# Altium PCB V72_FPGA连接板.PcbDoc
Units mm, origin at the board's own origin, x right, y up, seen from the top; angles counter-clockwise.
Board outline 27.69 x 52.7 mm, 2 copper layers (Top Layer, Bottom Layer); 0 components, 31 nets, 94 pads, 2 vias.
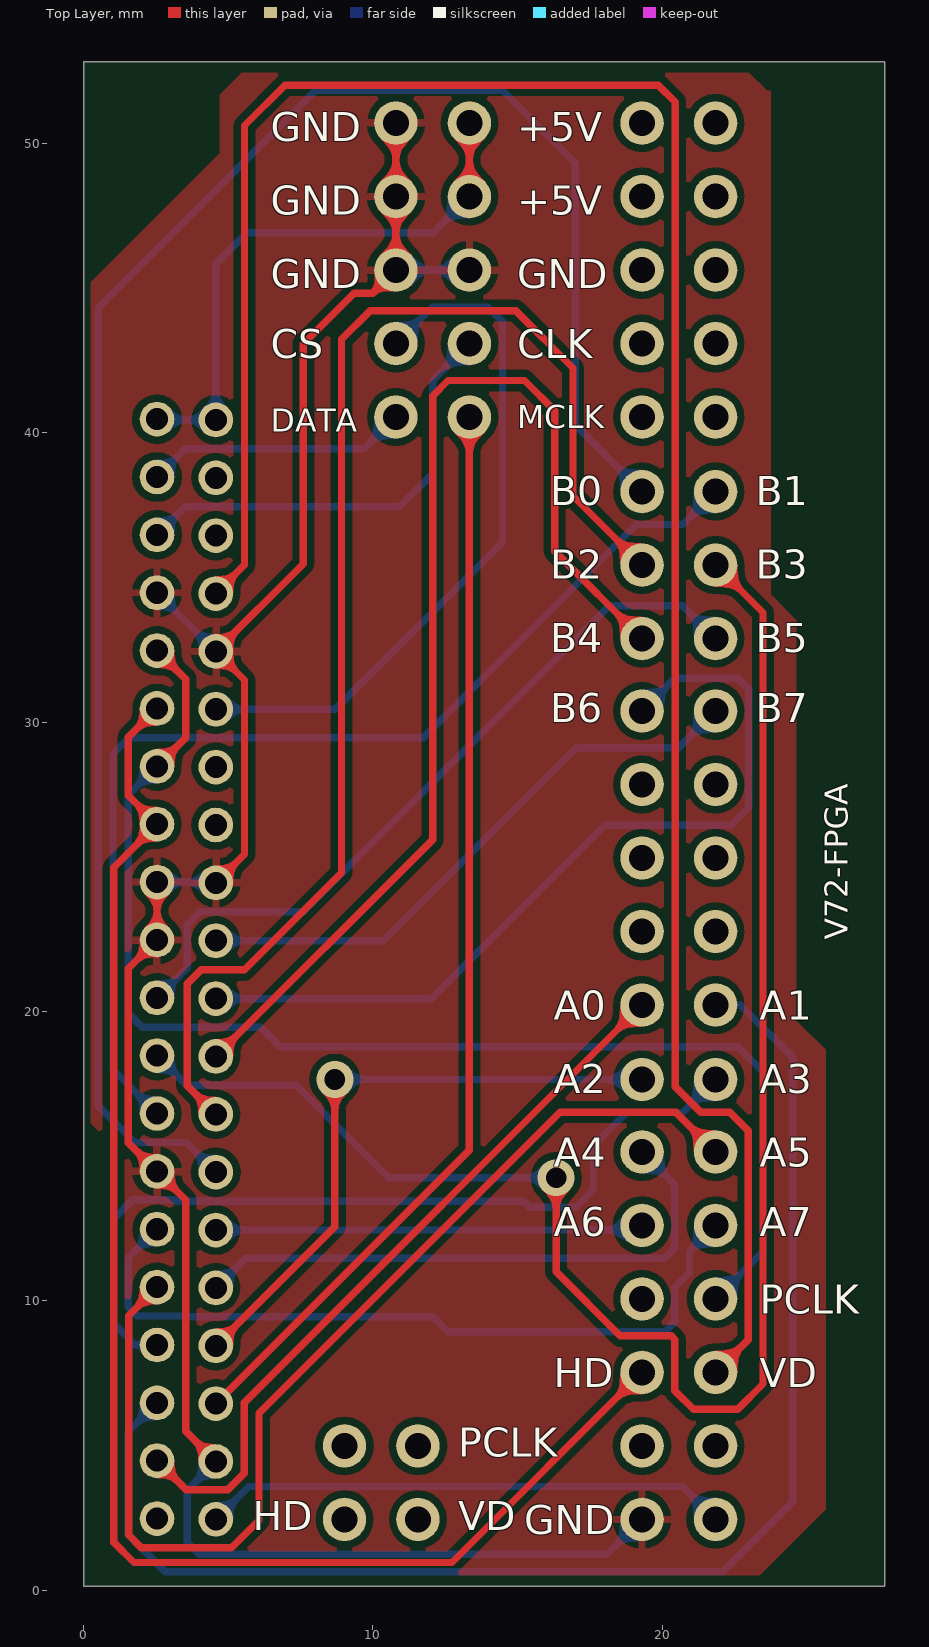
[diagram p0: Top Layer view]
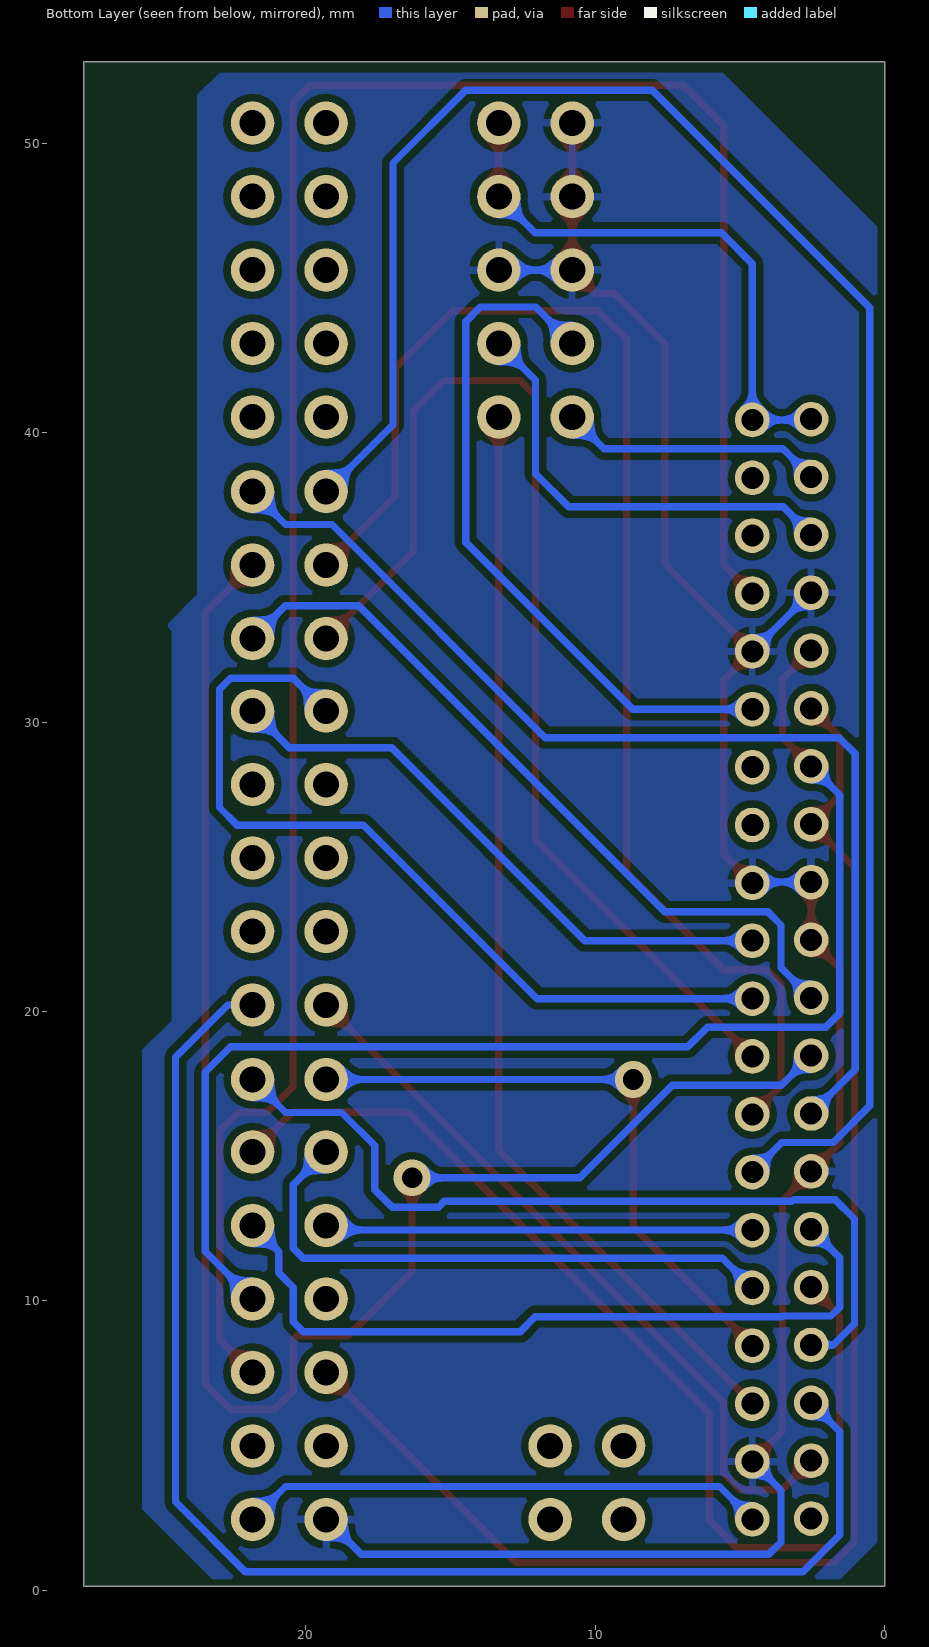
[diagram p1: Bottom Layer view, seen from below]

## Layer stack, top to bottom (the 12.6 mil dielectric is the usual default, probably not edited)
Top Solder: solder mask 0.0102, Solder Resist, Dk 3.5
Top Layer: signal copper 0.0356
Dielectric 1: dielectric 0.32, FR-4, Dk 4.8
Bottom Layer: signal copper 0.0356
Bottom Solder: solder mask 0.0102, Solder Resist, Dk 3.5

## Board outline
0,0.127 0,52.832 27.686,52.832 27.686,0.127

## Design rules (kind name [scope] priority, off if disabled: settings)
Clearance [All] p1: gap=0.254 ignorepadtopadclearanceinfootprint=FALSE except(0: Arc-Hole Track-Hole SMDPad-Hole THPad-Hole Via-Hole Fill-Hole Poly-Hole Region-Hole Text-Hole)
PolygonConnect [All] p1: connectstyle=Relief reliefconductorwidth=0.254 reliefentries=4 polygonreliefangle="90 Angle" airgapwidth=0.254
RoutingVias [All] p1: holewidth=0.711 width=1.27 viastyle="Through Hole" minholewidth=0.711 minwidth=1.27 maxholewidth=0.711 maxwidth=1.27
SolderMaskExpansion [All] p1: expansion=0.102
Width [All] p1: maxlimit=0.254 minlimit=0.254 preferedwidth=0.254
30 further rules are at their usual default settings.

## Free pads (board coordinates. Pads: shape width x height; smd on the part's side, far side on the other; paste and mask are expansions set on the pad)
  round 1.2 hole 0.762: 1(2.539,40.473) 2(4.572,40.445) 3(2.539,38.473) 4(4.572,38.445) 5(2.539,36.473) 6(4.572,36.445) 7(2.539,34.473) 8(4.572,34.445) 9(2.539,32.473) 10(4.572,32.445) 11(2.539,30.473) 12(4.572,30.445) 13(2.539,28.473) 14(4.572,28.445) 15(2.539,26.473) 16(4.572,26.445) 17(2.539,24.473) 18(4.572,24.445) 19(2.539,22.473) 20(4.572,22.445) 21(2.539,20.473) 22(4.572,20.445) 23(2.539,18.473) 24(4.572,18.445) 25(2.539,16.473) 26(4.572,16.445) 27(2.539,14.473) 28(4.572,14.445) 29(2.539,12.473) 30(4.572,12.445) 31(2.539,10.473) 32(4.572,10.445) 33(2.539,8.473) 34(4.572,8.445) 35(2.539,6.473) 36(4.572,6.445) 37(2.539,4.473) 38(4.572,4.445) 39(2.539,2.473) 40(4.572,2.445)
  round 1.5 hole 0.9: 1(21.844,2.445) 2(19.304,2.445) 3(21.844,4.985) 4(19.304,4.985) 5(11.557,2.445) 5(21.844,7.525) 6(9.017,2.445) 6(19.304,7.525) 7(11.557,4.985) 7(21.844,10.065) 8(9.017,4.985) 8(19.304,10.065) 9(21.844,12.605) 10(19.304,12.605) 11(21.844,15.145) 12(19.304,15.145) 13(21.844,17.649) 14(19.304,17.649) 15(21.844,20.225) 16(19.304,20.225) 17(21.844,22.765) 18(19.304,22.765) 19(21.844,25.305) 20(19.304,25.305) 21(21.844,27.845) 22(19.304,27.845) 23(21.844,30.385) 24(19.304,30.385) 25(21.844,32.889) 26(19.304,32.889) 27(21.844,35.429) 28(19.304,35.429) 29(21.844,37.969) 30(19.304,37.969) 31(13.335,40.545) 31(21.844,40.545) 32(10.795,40.545) 32(19.304,40.545) 33(13.335,43.085) 33(21.844,43.085) 34(10.795,43.085) 34(19.304,43.085) 35(13.335,45.625) 35(21.844,45.625) 36(10.795,45.625) 36(19.304,45.625) 37(13.335,48.165) 37(21.844,48.165) 38(10.795,48.165) 38(19.304,48.165) 39(13.335,50.705) 39(21.844,50.705) 40(10.795,50.705) 40(19.304,50.705)

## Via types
v1: diameter 1.27, hole 0.711, Top Layer to Bottom Layer, 2 vias

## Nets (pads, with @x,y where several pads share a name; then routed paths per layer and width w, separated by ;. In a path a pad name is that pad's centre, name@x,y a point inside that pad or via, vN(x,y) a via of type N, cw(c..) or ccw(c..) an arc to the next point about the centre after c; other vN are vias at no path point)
+5V: pad.1@2.539,40.473 pad.2@4.572,40.445 pad.37@13.335,48.165 pad.39@13.335,50.705 | length 19.7
  Top Layer w0.254: pad.37@13.335,48.165 pad.39@13.335,50.705
  Bottom Layer w0.254: pad.1@2.539,40.473 2.539,40.445 4.572,40.445 4.572,45.847 5.639,46.914 12.084,46.914 pad.37@13.335,48.165
A0: pad.16@19.304,20.225 pad.37@2.539,4.473 | length 25.6
  Top Layer w0.254: pad.37@2.539,4.473 3.548,3.464 4.978,3.464 5.553,4.039 5.553,6.474 pad.16@19.304,20.225
A1: pad.15@21.844,20.225 pad.35@2.539,6.473 | length 48.2
  Bottom Layer w0.254: pad.35@2.539,6.473 1.549,5.483 1.549,1.905 2.819,0.635 22.098,0.635 24.511,3.048 24.511,18.415 22.701,20.225 pad.15@21.844,20.225
A2: pad.14@19.304,17.649 pad.34@4.572,8.445 | length 21.5
  Top Layer w0.254: pad.34@4.572,8.445 8.687,12.56 v1(8.687,17.649)
  Bottom Layer w0.254: v1(8.687,17.649) pad.14@19.304,17.649
A3: pad.13@21.844,17.649 pad.33@2.539,8.473 | length 29.3
  Bottom Layer w0.254: pad.33@2.539,8.473 1.778,8.473 1.041,9.21 1.041,12.827 1.702,13.487 3.15,13.487 3.2,13.437 15.215,13.437 15.418,13.233 17.018,13.233 17.628,13.843 17.628,15.367 18.771,16.51 20.705,16.51 pad.13@21.844,17.649
A4: pad.12@19.304,15.145 pad.32@4.572,10.445 | length 20.2
  Bottom Layer w0.254: pad.32@4.572,10.445 5.601,11.474 20.098,11.474 20.435,11.811 20.435,14.014 pad.12@19.304,15.145
A5: pad.11@21.844,15.145 pad.31@2.539,10.473 | length 38.4
  Top Layer w0.254: pad.31@2.539,10.473 1.558,9.492 1.558,1.905 1.999,1.464 5.112,1.464 6.061,2.413 6.061,6.112 16.467,16.518 20.471,16.518 pad.11@21.844,15.145
A6: pad.10@19.304,12.605 pad.30@4.572,12.445 | length 14.8
  Bottom Layer w0.254: pad.30@4.572,12.445 19.144,12.445 pad.10@19.304,12.605
A7: pad.9@21.844,12.605 pad.29@2.539,12.473 | length 26.4
  Bottom Layer w0.254: pad.29@2.539,12.473 1.549,11.483 1.549,9.779 1.854,9.474 3.531,9.474 3.556,9.449 12.084,9.449 12.598,8.934 20.098,8.934 20.435,9.271 20.435,10.458 20.943,10.966 20.943,11.704 pad.9@21.844,12.605
B0: pad.28@4.572,14.445 pad.30@19.304,37.969 | length 65.6
  Bottom Layer w0.254: pad.28@4.572,14.445 3.548,15.469 1.778,15.469 0.508,16.739 0.508,44.323 8.026,51.841 14.478,51.841 16.993,49.327 16.993,40.28 pad.30@19.304,37.969
B1: pad.25@2.539,16.473 pad.29@21.844,37.969 | length 37.6
  Bottom Layer w0.254: pad.25@2.539,16.473 1.016,17.996 1.016,28.905 1.575,29.464 11.735,29.464 19.101,36.83 20.705,36.83 pad.29@21.844,37.969
B2: pad.26@4.572,16.445 pad.28@19.304,35.429 | length 47.3
  Top Layer w0.254: pad.26@4.572,16.445 3.581,17.436 3.581,20.955 4.064,21.438 5.563,21.438 8.915,24.79 8.915,43.231 9.906,44.221 14.935,44.221 16.916,42.24 16.916,37.817 pad.28@19.304,35.429
B3: pad.23@2.539,18.473 pad.27@21.844,35.429 | length 58.3
  Top Layer w0.254: v1(16.332,14.249) 16.332,10.998 18.542,8.788 20.308,8.788 20.435,8.661 20.435,6.895 21.082,6.248 22.606,6.248 23.483,7.125 23.483,33.79 pad.27@21.844,35.429
  Bottom Layer w0.254: pad.23@2.539,18.473 3.562,17.45 7.341,17.45 10.541,14.249 v1(16.332,14.249)
B4: pad.24@4.572,18.445 pad.26@19.304,32.889 | length 39.9
  Top Layer w0.254: pad.24@4.572,18.445 12.065,25.938 12.065,41.275 12.598,41.808 15.24,41.808 16.281,40.767 16.281,35.912 pad.26@19.304,32.889
B5: pad.21@2.539,20.473 pad.25@21.844,32.889 | length 26.2
  Bottom Layer w0.254: pad.21@2.539,20.473 3.581,21.515 3.581,22.987 4.039,23.444 7.595,23.444 18.17,34.02 20.713,34.02 pad.25@21.844,32.889
B6: pad.22@4.572,20.445 pad.24@19.304,30.385 | length 29.5
  Bottom Layer w0.254: pad.22@4.572,20.445 12.012,20.445 18.009,26.441 22.377,26.441 22.987,27.051 22.987,31.135 22.606,31.516 20.435,31.516 pad.24@19.304,30.385
B7: pad.20@4.572,22.445 pad.23@21.844,30.385 | length 20.6
  Bottom Layer w0.254: pad.20@4.572,22.445 10.363,22.445 17.033,29.115 20.574,29.115 pad.23@21.844,30.385
CS_SPI: pad.12@4.572,30.445 pad.34@10.795,43.085 | length 24.3
  Bottom Layer w0.254: pad.12@4.572,30.445 8.703,30.445 14.478,36.22 14.478,43.84 13.97,44.348 12.058,44.348 pad.34@10.795,43.085
FRAME_START: pad.16@4.572,26.445
GND: pad.2@19.304,2.445 pad.7@2.539,34.473 pad.10@4.572,32.445 pad.17@2.539,24.473 pad.18@4.572,24.445 pad.19@2.539,22.473 pad.27@2.539,14.473 pad.35@13.335,45.625 pad.36@10.795,45.625 pad.38@4.572,4.445 pad.38@10.795,48.165 pad.40@10.795,50.705 | length 78.8
  Top Layer w0.254: pad.17@2.539,24.473 2.539,22.473 1.549,21.483 1.549,15.463 2.539,14.473 3.531,13.481 3.531,5.486 pad.38@4.572,4.445 ; pad.18@4.572,24.445 5.563,25.436 5.563,31.454 4.572,32.445 7.595,35.468 7.595,43.071 9.347,44.823 9.993,44.823 10.795,45.625 10.795,48.165 pad.40@10.795,50.705
  Bottom Layer w0.254: pad.17@2.539,24.473 4.572,24.473 pad.18@4.572,24.445 ; pad.7@2.539,34.473 3.535,33.477 3.54,33.477 pad.10@4.572,32.445 ; pad.38@4.572,4.445 3.581,3.454 3.581,1.651 3.998,1.234 18.093,1.234 pad.2@19.304,2.445 ; pad.36@10.795,45.625 pad.35@13.335,45.625
HD: pad.6@19.304,7.525 pad.11@2.539,30.473 pad.15@2.539,26.473 | length 51.5
  Top Layer w0.254: pad.11@2.539,30.473 1.549,29.483 1.549,27.463 2.539,26.473 1.041,24.975 1.041,1.66 1.745,0.956 12.735,0.956 pad.6@19.304,7.525
I2C_CLK(SCL): pad.5@2.539,36.473 pad.33@13.335,43.085 | length 15.4
  Bottom Layer w0.254: pad.5@2.539,36.473 3.506,37.44 10.922,37.44 12.065,38.583 12.065,41.815 pad.33@13.335,43.085
I2C_Data(SDI): pad.3@2.539,38.473 pad.32@10.795,40.545 | length 9.1
  Bottom Layer w0.254: pad.3@2.539,38.473 3.512,39.446 9.696,39.446 pad.32@10.795,40.545
MAIN_RES: pad.6@4.572,36.445
MCLK: pad.31@13.335,40.545 pad.36@4.572,6.445 | length 37.7
  Top Layer w0.254: pad.36@4.572,6.445 13.335,15.208 pad.31@13.335,40.545
MODULE_RST: pad.4@4.572,38.445
PCLK: pad.7@21.844,10.065 pad.9@2.539,32.473 pad.13@2.539,28.473 | length 45.1
  Top Layer w0.254: pad.13@2.539,28.473 3.531,29.465 3.531,31.481 pad.9@2.539,32.473
  Bottom Layer w0.254: pad.13@2.539,28.473 1.549,27.483 1.549,19.939 2.032,19.456 6.121,19.456 6.798,18.78 22.61,18.78 23.483,17.907 23.483,11.704 pad.7@21.844,10.065
ROLLER_OUT: pad.14@4.572,28.445
TP0: pad.39@2.539,2.473
TP1: pad.1@21.844,2.445 pad.40@4.572,2.445 | length 18.2
  Bottom Layer w0.254: pad.40@4.572,2.445 5.708,3.581 20.708,3.581 pad.1@21.844,2.445
VD: pad.5@21.844,7.525 pad.8@4.572,34.445 | length 78.3
  Top Layer w0.254: pad.8@4.572,34.445 5.563,35.436 5.563,50.622 6.96,52.019 19.863,52.019 20.447,51.435 20.447,17.399 21.328,16.518 22.332,16.518 22.975,15.875 22.975,8.656 pad.5@21.844,7.525

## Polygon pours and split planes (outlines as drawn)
GND on Top Layer "Top Layer-GND" (solid, pour order 0): 22.987,52.451 23.622,51.816 23.749,51.816 23.749,34.417 24.638,33.528 24.638,19.685 25.654,18.669 25.654,2.794 23.368,0.508 1.651,0.508 0.635,1.524 0.635,15.748 0.254,16.129 0.254,45.212 4.699,49.657 4.699,51.689 5.461,52.451
GND on Bottom Layer "Top Layer-GND" (solid, pour order 2): 5.588,52.451 22.987,52.451 23.749,51.689 23.749,34.417 24.765,33.401 24.765,33.274 24.638,33.147 24.638,19.685 25.654,18.669 25.654,2.794 23.241,0.381 1.524,0.381 0.254,1.651 0.254,47.117

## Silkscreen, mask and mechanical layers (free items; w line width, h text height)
Top Overlay:
  text "GND" at 6.477,50.07 h1
  text "+5V" at 14.986,50.07 h1
  text "GND" at 6.477,47.53 h1
  text "+5V" at 14.986,47.53 h1
  text "GND" at 6.477,44.99 h1
  text "GND" at 14.986,44.99 h1
  text "CS" at 6.477,42.577 h1
  text "CLK" at 14.986,42.577 h1
  text "MCLK" at 14.986,40.164 h0.8
  text "DATA" at 6.477,40.037 h0.8
  text "B0" at 16.129,37.497 h1
  text "B1" at 23.241,37.497 h1
  text "B2" at 16.129,34.957 h1
  text "B3" at 23.241,34.957 h1
  text "B4" at 16.129,32.417 h1
  text "B5" at 23.241,32.417 h1
  text "B6" at 16.129,30.004 h1
  text "B7" at 23.241,30.004 h1
  text "V72-FPGA" at 26.416,22.479 h0.8 r90
  text "A0" at 16.256,19.717 h1
  text "A1" at 23.368,19.717 h1
  text "A2" at 16.256,17.177 h1
  text "A3" at 23.368,17.177 h1
  text "A4" at 16.256,14.637 h1
  text "A5" at 23.368,14.637 h1
  text "A6" at 16.256,12.224 h1
  text "A7" at 23.368,12.224 h1
  text "PCLK" at 23.368,9.557 h1
  text "HD" at 16.256,7.017 h1
  text "VD" at 23.368,7.017 h1
  text "PCLK" at 12.954,4.604 h1
  text "HD" at 5.842,2.064 h1
  text "VD" at 12.954,2.064 h1
  text "GND" at 15.24,1.937 h1
Mechanical 1:
  the board outline again, w0.254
